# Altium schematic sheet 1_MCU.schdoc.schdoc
size 309 x 223 mm; Symbol: Sheet-Symbol_A4; Device: Sheet-Symbol_A4; Company: EasyEDA.com; Drawed: EasyEDA Pro; Reviewed: EasyEDA Pro; Version: V2.3; Page Size: A4; @Project Name: RecoveryBoard_W24Edits; @Page Count: 3; @Update Date: 2024-02-20; @Create Date: 2024-01-31; @Schematic Name: Schematic; Part Number: JLCPCB-002; @Page No: 1; @Page Name: MCU
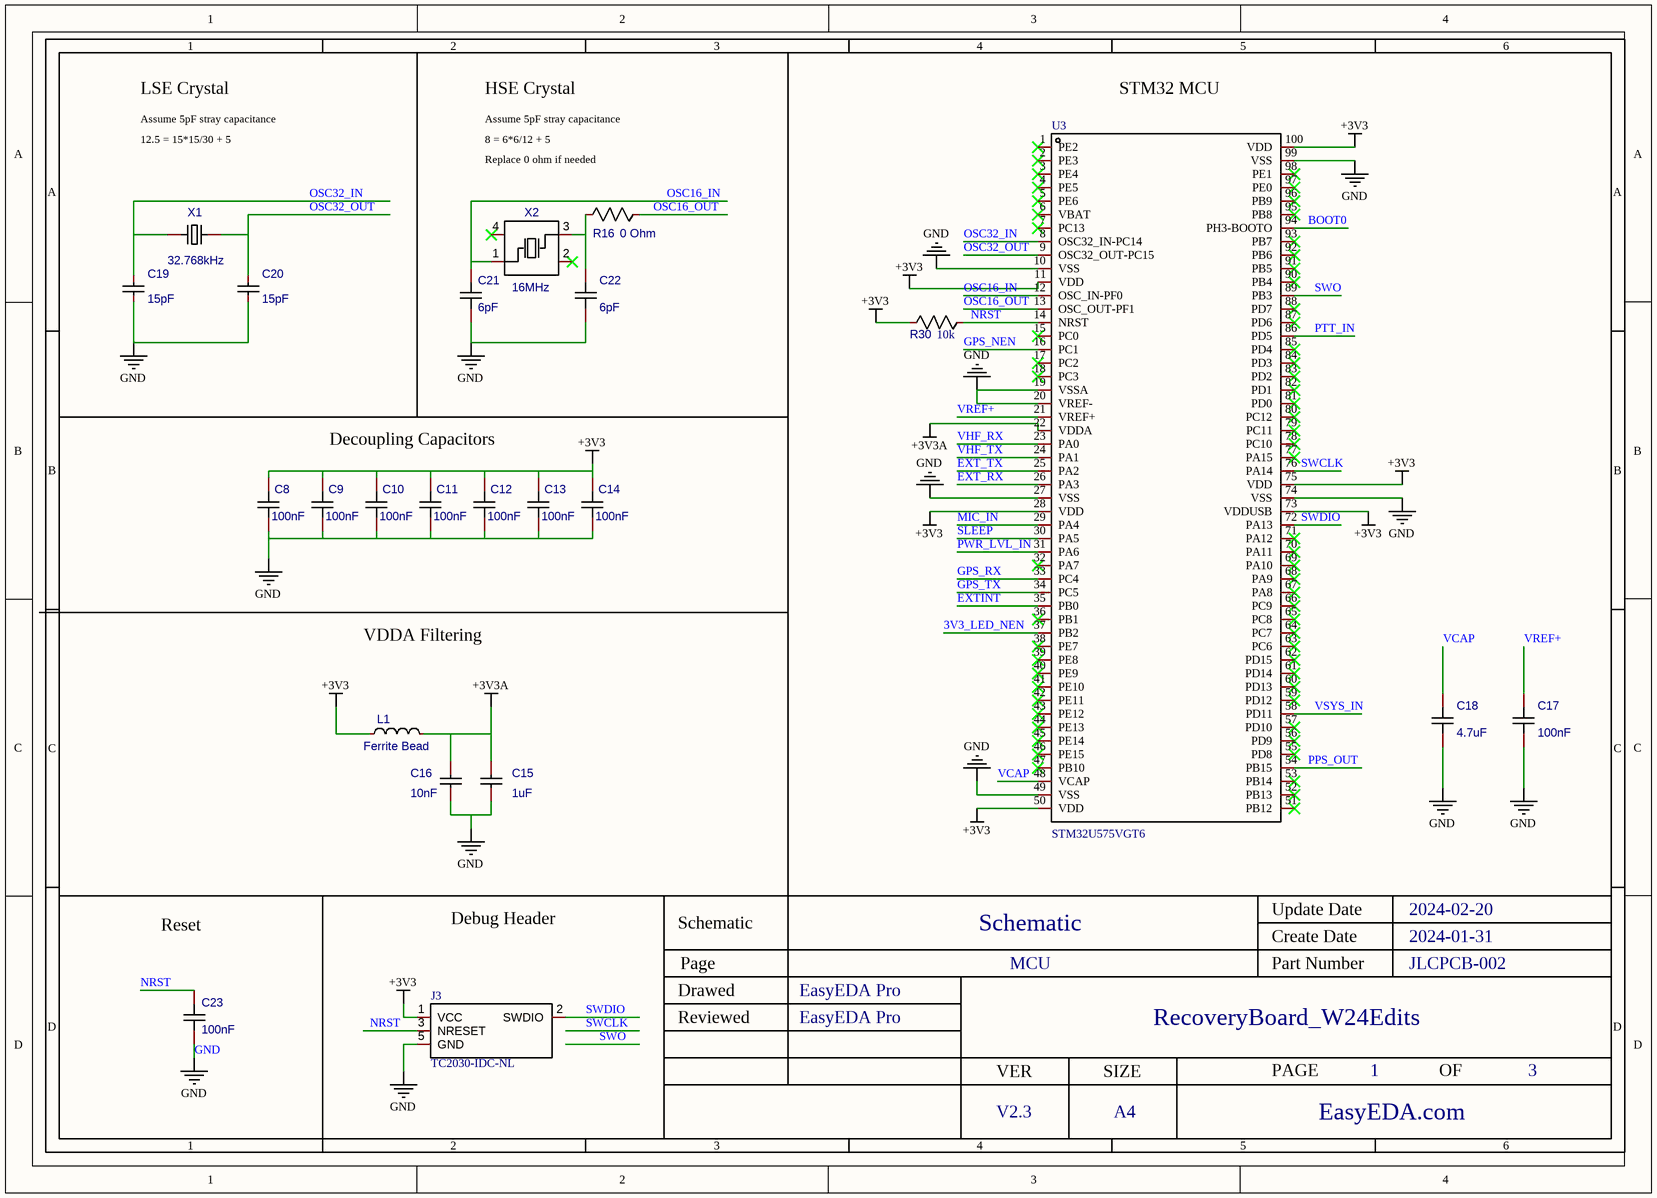
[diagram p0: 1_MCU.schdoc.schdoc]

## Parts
C8  100nF  [C0402]
C9  100nF  [C0402]
C10  100nF  [C0402]
C11  100nF  [C0402]
C12  100nF  [C0402]
C13  100nF  [C0402]
C14  100nF  [C0402]
C15  1uF  [C0402]
C16  10nF  [C0402]
C17  100nF  [C0402]
C18  4.7uF  [C0603]
C19  15pF  [C0402]
C20  15pF  [C0402]
C21  6pF  [C0402]
C22  6pF  [C0402]
C23  100nF  [C0402]
J3  TC2030-IDC-NL  [TC2030-IDC-NL]
L1  Ferrite Bead  [L0603]
R16  0 Ohm  [R0603]
R30  10k  [R0603]
U3  STM32U575VGT6  [LQFP-100_L14.0-W14.0-P0.50-LS16.0-BL]
X1  32.768kHz  [OSC-SMD_L3.2-W1.5]
X2  16MHz  [CRYSTAL-SMD_4P-L2.5-W2.0-BL-A]

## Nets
+3V3: C8.2 C9.2 C10.2 C11.2 C12.2 C13.2 C14.2 J3.1(VCC) L1.2 R30.1 U3.11(VDD) U3.28(VDD) U3.50(VDD) U3.73(VDDUSB) U3.75(VDD) U3.100(VDD)
+3V3A: C15.2 C16.2 L1.1 U3.22(VDDA)
GND: C8.1 C9.1 C10.1 C11.1 C12.1 C13.1 C14.1 C15.1 C16.1 C17.1 C18.1 C19.1 C20.1 C21.1 C22.1 C23.1 J3.5(GND) U3.10(VSS) U3.19(VSSA) U3.20(VREF-) U3.27(VSS) U3.49(VSS) U3.74(VSS) U3.99(VSS)
3V3_LED_NEN: U3.37(PB2)
BOOT0: U3.94(PH3-BOOTO)
EXT_RX: U3.26(PA3)
EXT_TX: U3.25(PA2)
EXTINT: U3.35(PB0)
GPS_NEN: U3.16(PC1)
GPS_RX: U3.33(PC4)
GPS_TX: U3.34(PC5)
MIC_IN: U3.29(PA4)
NRST: C23.2 J3.3(NRESET) R30.2 U3.14(NRST)
OSC16_IN: C21.2 U3.12(OSC_IN-PF0) X2.1
OSC16_OUT: R16.2 U3.13(OSC_OUT-PF1)
OSC32_IN: C19.2 U3.8(OSC32_IN-PC14) X1.1
OSC32_OUT: C20.2 U3.9(OSC32_OUT-PC15) X1.2
PPS_OUT: U3.54(PB15)
PTT_IN: U3.86(PD5)
PWR_LVL_IN: U3.31(PA6)
SLEEP: U3.30(PA5)
SWCLK: U3.76(PA14)
SWDIO: J3.2(SWDIO) U3.72(PA13)
SWO: U3.89(PB3)
VCAP: C18.2 U3.48(VCAP)
VHF_RX: U3.23(PA0)
VHF_TX: U3.24(PA1)
VREF+: C17.2 U3.21(VREF+)
VSYS_IN: U3.58(PD11)
NetC22_2: C22.2 R16.1 X2.3

Not connected (* = marked no-connect by the designer): J3 4(SWCLK) 6(SWO); U3 1(PE2)* 2(PE3)* 3(PE4)* 4(PE5)* 5(PE6)* 6(VBAT)* 7(PC13)* 15(PC0)* 17(PC2)* 18(PC3)* 32(PA7)* 36(PB1)* 38(PE7)* 39(PE8)* 40(PE9)* 41(PE10)* 42(PE11)* 43(PE12)* 44(PE13)* 45(PE14)* 46(PE15)* 47(PB10)* 51(PB12)* 52(PB13)* 53(PB14)* 55(PD8)* 56(PD9)* 57(PD10)* 59(PD12)* 60(PD13)* 61(PD14)* 62(PD15)* 63(PC6)* 64(PC7)* 65(PC8)* 66(PC9)* 67(PA8)* 68(PA9)* 69(PA10)* 70(PA11)* 71(PA12)* 77(PA15)* 78(PC10)* 79(PC11)* 80(PC12)* 81(PD0)* 82(PD1)* 83(PD2)* 84(PD3)* 85(PD4)* 87(PD6)* 88(PD7)* 90(PB4)* 91(PB5)* 92(PB6)* 93(PB7)* 95(PB8)* 96(PB9)* 97(PE0)* 98(PE1)*; X2 2(GND)* 4(GND)*

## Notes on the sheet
- 12.5 = 15*15/30 + 5
- Assume 5pF stray capacitance
- LSE Crystal
- HSE Crystal
- 8 = 6*6/12 + 5
- (near U3) STM32 MCU
- Replace 0 ohm if needed
- Decoupling Capacitors
- VDDA Filtering
- Reset
- Debug Header

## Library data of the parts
C8-C14 C17 C23 = GRM155R71C104KA88D: Manufacturer: muRata(村田); Convert to PCB: yes
C15 = GRM155R61E105KA12D: Manufacturer: muRata(村田); Convert to PCB: yes
C16 = GRM155R71H103KA88D: Manufacturer: muRata(村田); Convert to PCB: yes
C18 = GRM188R61A475KE15D: Manufacturer: muRata(村田); Convert to PCB: yes
C19 C20 = GJM1555C1H150FB01D: Manufacturer: muRata(村田); Convert to PCB: yes
C21 C22 = GCM1555C1H6R0BA16D: Manufacturer: muRata(村田); Convert to PCB: yes
J3 = TC2030-IDC-NL: Add into BOM: yes; _: 3
L1 = BLM18PG121SN1D: Manufacturer: muRata(村田); Value: 120R; Convert to PCB: yes
R16 = 0603WAF0000T5E: Convert to PCB: yes
R30 = RC0603FR-0710KL: Convert to PCB: yes
U3 = STM32U575VGT6: Manufacturer: ST(意法半导体); Add into BOM: yes
X1 = X321532768KGD2SI: Manufacturer: YXC(扬兴晶振); Convert to PCB: yes
X2 = NX2520SA-16MHZ-STD-CSW-5: Manufacturer: NDK; Convert to PCB: yes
